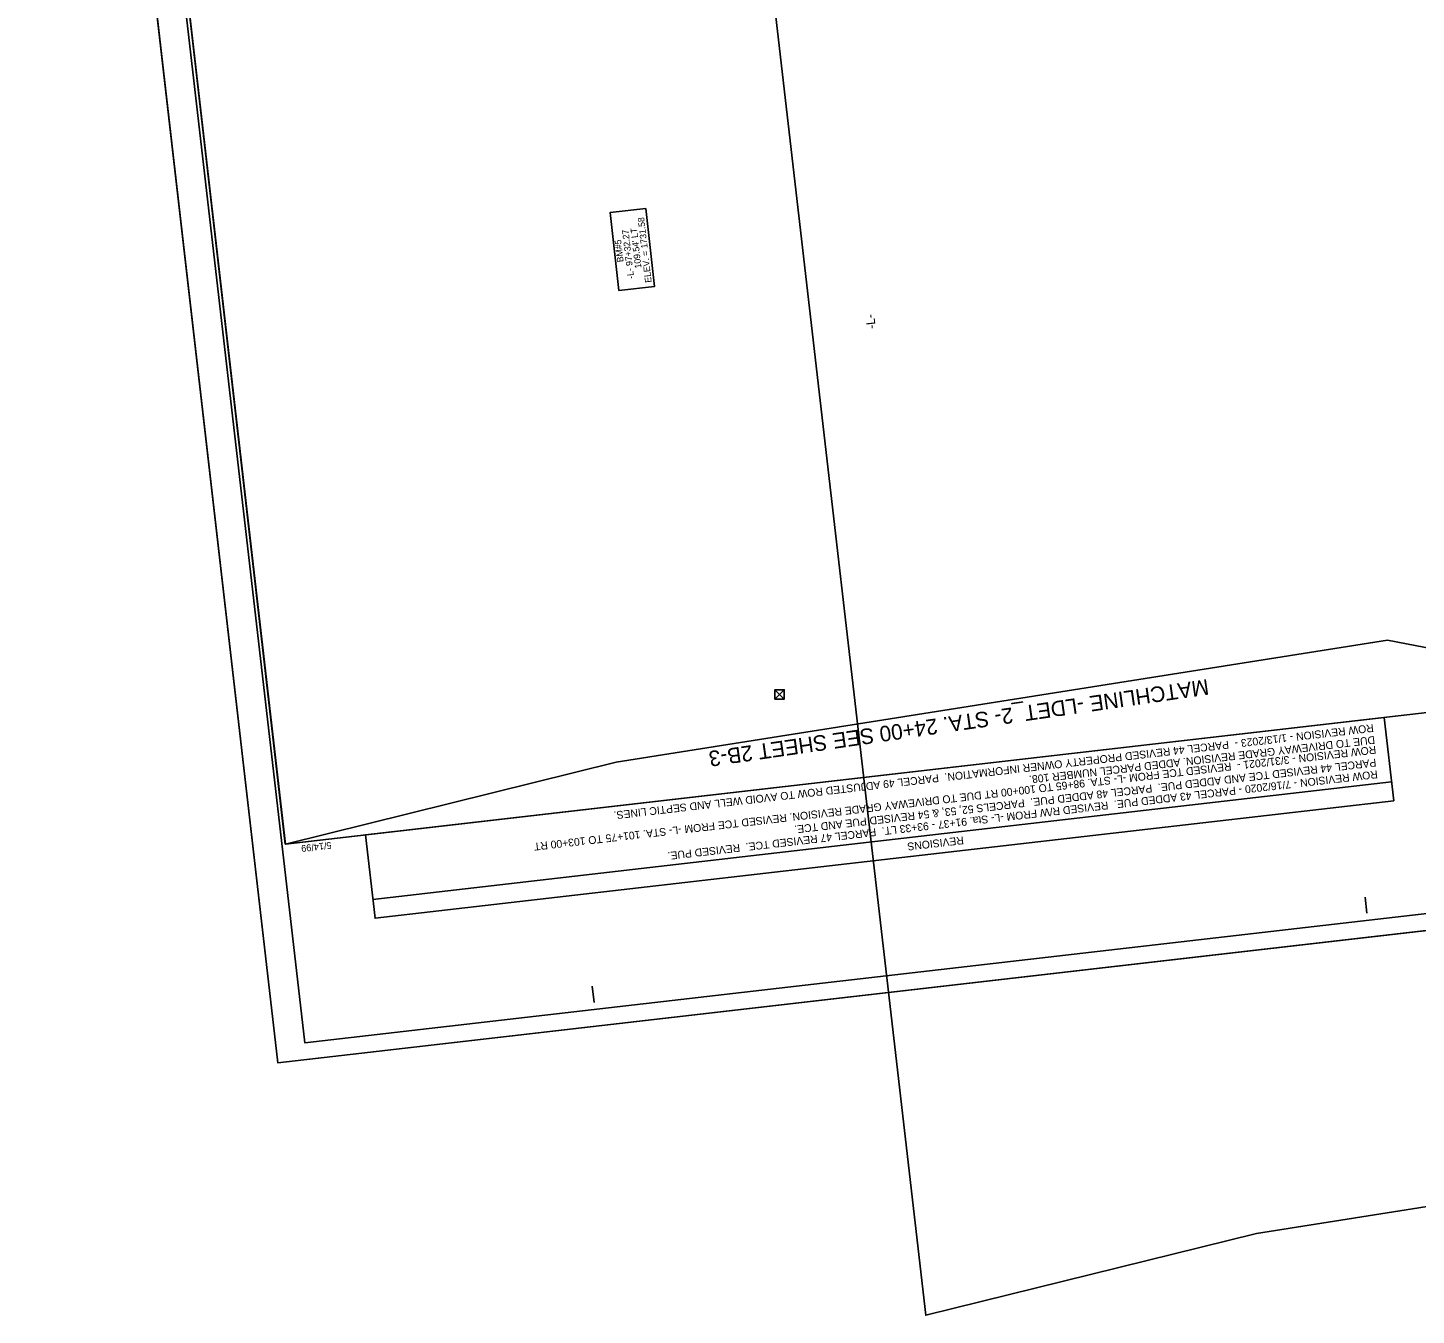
# Model space of a CAD drawing. Extents: x 477607 to 479438, y 495543 to 499482.
# Drawn here: x 477607 to 478677, y 495543 to 496535 of the extents above; entities that cross this region are included whole.
import ezdxf

# ---------------------------------------------------------------- set-up
doc = ezdxf.new("R2010")
doc.units = 0
for name, color, linetype in [('Default', 7, 'Continuous'), ('Matchline', 7, 'Continuous'), ('Matchline Text', 7, 'Continuous'), ('Prop Dimension Text', 7, 'Continuous'), ('Prop Grid Mask', 7, 'Continuous'), ('Prop Horizontal Alignment Station Label', 7, 'Continuous'), ('Sheet Block Revision CELL', 7, 'Continuous'), ('Sheet Border Standard 30in CELL', 7, 'Continuous'), ('Sheet Cutting Line CELL', 7, 'Continuous'), ('Sheet Layout Plan Border', 7, 'Continuous'), ('Sheet Plan CELL', 7, 'Continuous'), ('Sheet Plot Border Inside CELL', 7, 'Continuous'), ('Sheet Plot Border Outside CELL', 7, 'Continuous')]:
    doc.layers.add(name, color=color, linetype=linetype)

msp = doc.modelspace()

# ---------------------------------------------------------------- linework, layer by layer
at = {"layer": 'Default'}
msp.add_line((478186.6, 496021.3), (478186.6, 496021.3), dxfattribs=at)
msp.add_lwpolyline([(478183, 496024.9), (478190.2, 496024.9), (478190.2, 496017.7), (478183, 496017.7)], close=True, dxfattribs=at)
for points in [[(478190.2, 496024.9), (478183, 496017.7), (478186.6, 496021.3), (478190.2, 496017.7), (478183, 496024.9)], [(478186.6, 496021.3), (478190.2, 496024.9), (478183, 496024.9), (478186.6, 496021.3)], [(478186.6, 496021.3), (478183, 496017.7), (478190.2, 496017.7), (478186.6, 496021.3)]]:
    msp.add_lwpolyline(points, dxfattribs=at)
at = {"layer": 'Matchline'}
msp.add_line((478655.3, 496063.1), (478060.6, 495969), dxfattribs=at)
at = {"layer": 'Prop Grid Mask'}
msp.add_lwpolyline([(478062.7, 496332.7), (478055.8, 496392.8), (478083.3, 496395.9), (478090.2, 496335.9)], close=True, dxfattribs=at)
at = {"layer": 'Sheet Block Revision CELL'}
msp.add_line((478658.4, 495953.9), (477873, 495863.3), dxfattribs=at)
msp.add_lwpolyline([(478660.1, 495939.4), (477874.7, 495848.8), (477867.2, 495913), (478652.7, 496003.6)], close=True, dxfattribs=at)
at = {"layer": 'Sheet Border Standard 30in CELL'}
for p, q in [((477805.3, 495906.9), (477805.3, 495906.9)), ((478639.5, 495852.6), (478638.1, 495865)), ((478043.5, 495783.9), (478042, 495796.3))]:
    msp.add_line(p, q, dxfattribs=at)
msp.add_lwpolyline([(477633.6, 497396), (477805.4, 495905.9), (478848.5, 496026.2), (478676.7, 497516.3)], close=True, dxfattribs=at)
at = {"layer": 'Sheet Cutting Line CELL'}
for p, q in [((477606.8, 497410.1), (477799.7, 495737.2)), ((477799.7, 495737.2), (478892.5, 495863.1))]:
    msp.add_line(p, q, dxfattribs=at)
at = {"layer": 'Sheet Layout Plan Border'}
for points in [[(478060.6, 495969), (478655.3, 496063.1), (478848.5, 496026), (478736, 497002.1), (478709.9, 496998.3), (478420.1, 496964.9), (478384.1, 497277.1), (478673.9, 497310.5), (478699.8, 497316.3), (478696.2, 497346.9), (478616.7, 497337.7), (478607.5, 497417.9), (478188.5, 497393.4), (477955.4, 497379.7), (477811.2, 497371.3), (477828.9, 497217.2), (477697.9, 497202.1), (477716.3, 497043.3), (477674.8, 497038.5), (477805.5, 495905.9)], [(478060.6, 495969), (478655.3, 496063.1), (478848.5, 496026), (478736, 497002.1), (478709.9, 496998.3), (478420.1, 496964.9), (478384.1, 497277.1), (478673.9, 497310.5), (478699.8, 497316.3), (478696.2, 497346.9), (478616.7, 497337.7), (478607.5, 497417.9), (478188.5, 497393.4), (477955.4, 497379.7), (477811.2, 497371.3), (477828.9, 497217.2), (477697.9, 497202.1), (477716.3, 497043.3), (477674.8, 497038.5), (477805.5, 495905.9)], [(478554.4, 495605.7), (479149, 495699.8), (479342.3, 495662.8), (479229.8, 496638.8), (479203.7, 496635.1), (478913.9, 496601.6), (478877.9, 496913.8), (479167.7, 496947.3), (479193.5, 496953.1), (479190, 496983.6), (479110.5, 496974.5), (479101.3, 497054.6), (478682.2, 497030.1), (478449.2, 497016.5), (478304.9, 497008), (478322.7, 496854), (478191.7, 496838.8), (478210.1, 496680.1), (478168.6, 496675.3), (478299.2, 495542.6)]]:
    msp.add_lwpolyline(points, close=True, dxfattribs=at)
at = {"layer": 'Sheet Plan CELL'}
msp.add_line((477815.1, 495821.7), (477815.1, 495821.7), dxfattribs=at)
for points in [[(477633.6, 497396.1), (477805.4, 495905.9), (478848.5, 496026.2), (478676.7, 497516.3)], [(478848.5, 496026.2), (477805.5, 495905.9), (477656.5, 497197.3), (477805.6, 497214.5), (477782.7, 497413.2), (478676.7, 497516.3)]]:
    msp.add_lwpolyline(points, close=True, dxfattribs=at)
at = {"layer": 'Sheet Plot Border Inside CELL'}
msp.add_lwpolyline([(477629.6, 497408.2), (477820.5, 495752.6), (478868.7, 495873.5), (478677.8, 497529)], close=True, dxfattribs=at)
at = {"layer": 'Sheet Plot Border Outside CELL'}
msp.add_lwpolyline([(477606.8, 497410.1), (477799.7, 495737.2), (478892.5, 495863.1), (478699.6, 497536.1)], close=True, dxfattribs=at)

# ---------------------------------------------------------------- texts
at = {"layer": 'Matchline Text'}
msp.add_text('MATCHLINE -LDET_2- STA. 24+00 SEE SHEET 2B-3', height=12, rotation=188.237, dxfattribs=at).set_placement((478516.6, 496033.2))
at = {"layer": 'Prop Dimension Text'}
for s, p in [('ELEV. = 1731.58 ', (478087.9, 496339.1)), ('-L- 97+32.27', (478074.4, 496342.1)), ("109.54' LT", (478080.1, 496350.1)), ('BM#5', (478066.3, 496354.9))]:
    msp.add_text(s, height=5, rotation=96.5773, dxfattribs=at).set_placement(p)
at = {"layer": 'Prop Horizontal Alignment Station Label'}
msp.add_text('-L-', height=7, rotation=96.5773, dxfattribs=at).set_placement((478260.8, 496303.5))
at = {"layer": 'Sheet Block Revision CELL'}
for s, rotation, p in [('ROW REVISION - 1/13/2023 -  PARCEL 44 REVISED PROPERTY OWNER INFORMATION.  PARCEL 49 ADJUSTED ROW TO AVOID WELL AND SEPTIC LINES.', 186.5773, (478644.3, 495998.5)), ('DUE TO DRIVEWAY GRADE REVISION. ADDED PARCEL NUMBER 108. ', 186.5773, (478645.3, 495989.3)), ('ROW REVISION - 3/31/2021 -  REVISED TCE FROM -L- STA. 98+65 TO 100+00 RT DUE TO DRIVEWAY GRADE REVISION. REVISED TCE FROM -L- STA. 101+75 TO 103+00 RT ', 186.5773, (478646.2, 495981.7)), ('PARCEL 44 REVISED TCE AND ADDED PUE.  PARCEL 48 ADDED PUE.  PARCELS 52, 53, & 54 REVISED PUE AND TCE. ', 186.5787, (478646.3, 495971.8)), ('ROW REVISION - 7/16/2020 - PARCEL 43 ADDED PUE.  REVISED R/W FROM -L- Sta. 91+37 - 93+33 LT.  PARCEL 47 REVISED TCE.  REVISED PUE.', 186.5787, (478647.4, 495962.8)), ('REVISIONS', 186.6074, (478328.2, 495911.9))]:
    msp.add_text(s, height=6, rotation=rotation, dxfattribs=at).set_placement(p)
at = {"layer": 'Sheet Border Standard 30in CELL'}
msp.add_text('5/14/99', height=5.25, rotation=186.5773, dxfattribs=at).set_placement((477840.7, 495907.7))

doc.saveas('drawing.dxf')
